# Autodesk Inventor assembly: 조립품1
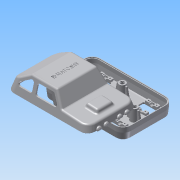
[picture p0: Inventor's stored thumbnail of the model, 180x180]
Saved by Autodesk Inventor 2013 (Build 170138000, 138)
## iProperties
Created: 2015-05
Part Number: 조립품1
Document SubType Name: Assembly
Designer: Administrator
Author: Administrator
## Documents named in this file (3)
- C:\Documents and Settings\Administrator\바탕 화면\450507V1030\조립품1.iam
- C:\Documents and Settings\Administrator\바탕 화면\450507V1030\1-본체.ipt
- C:\Documents and Settings\Administrator\바탕 화면\450507V1030\커버.ipt
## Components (1 placed, 1 different names)
1. 1-본체:1
